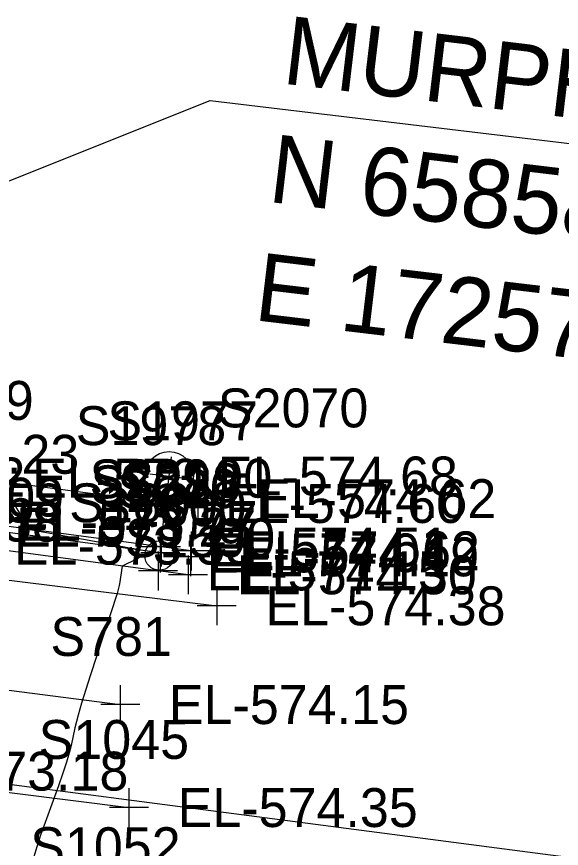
# Model space of a CAD drawing. Extents: x 1724534 to 1727318, y 657156 to 660047.
# Drawn here: x 1725905.5 to 1725961.5, y 658565.7 to 658651.2 of the extents above; entities that cross this region are included whole.
import ezdxf

# ---------------------------------------------------------------- set-up
doc = ezdxf.new("R2010")
doc.units = 0
for name, color, linetype in [('SURVEY - CENTERLINE - Preliminary Text', 7, 'Continuous'), ('SURVEY - CONTOURS - Intermediate with optional Text', 7, 'Continuous'), ('SURVEY - DTM - Breaklines', 7, 'Continuous'), ('SURVEY - DTM - Breaklines - Points - Elevations', 7, 'Continuous'), ('SURVEY - DTM - Breaklines - Points - Locators', 7, 'Continuous'), ('SURVEY - DTM - Breaklines - Points - Numbers', 7, 'Continuous'), ('SURVEY - TRAFFIC CONTROL - Pavement Marking - Points - Elevations', 7, 'Continuous'), ('SURVEY - TRAFFIC CONTROL - Pavement Marking - Points - Locators', 7, 'Continuous'), ('SURVEY - TRAFFIC CONTROL - Pavement Marking - Points - Numbers', 7, 'Continuous'), ('SURVEY - TRAFFIC CONTROL - Pavement Marking with Text', 7, 'Continuous'), ('SURVEY - TRANSPORTATION - Features', 7, 'Continuous'), ('SURVEY - TRANSPORTATION - Features - Points - Elevations', 7, 'Continuous'), ('SURVEY - TRANSPORTATION - Features - Points - Locators', 7, 'Continuous'), ('SURVEY - TRANSPORTATION - Features - Points - Numbers', 7, 'Continuous'), ('SURVEY - TRANSPORTATION - Roads', 7, 'Continuous'), ('SURVEY - TRANSPORTATION - Roads - Points - Elevations', 7, 'Continuous'), ('SURVEY - TRANSPORTATION - Roads - Points - Locators', 7, 'Continuous'), ('SURVEY - TRANSPORTATION - Roads - Points - Numbers', 7, 'Continuous'), ('SURVEY - UTILITIES - Electric (Lighting) - Points - Elevations', 7, 'Continuous'), ('SURVEY - UTILITIES - Electric (Lighting) - Points - Locators', 7, 'Continuous'), ('SURVEY - UTILITIES - Electric (Lighting) - Points - Numbers', 7, 'Continuous'), ('SURVEY - UTILITIES - Electric (Lighting) with Text', 7, 'Continuous'), ('SURVEY - UTILITIES - Water with Text', 7, 'Continuous')]:
    doc.layers.add(name, color=color, linetype=linetype)

msp = doc.modelspace()

# ---------------------------------------------------------------- linework, layer by layer
at = {"layer": 'SURVEY - CENTERLINE - Preliminary Text'}
for p, q in [((1725772.853, 658581.708), (1725925.415, 658642.543)), ((1725925.415, 658642.543), (1726126.989, 658618.518))]:
    msp.add_line(p, q, dxfattribs=at)
at = {"layer": 'SURVEY - CONTOURS - Intermediate with optional Text'}
msp.add_lwpolyline([(1725904.993, 658601.596), (1725905.542, 658600.595), (1725905.788, 658600.157), (1725905.89, 658599.981), (1725906.23, 658599.394), (1725906.31, 658599.252), (1725906.379, 658599.122), (1725906.439, 658599.005), (1725906.695, 658598.491), (1725909.713, 658597.944), (1725911.185, 658597.675), (1725912.581, 658597.422), (1725913.679, 658597.22), (1725914.63, 658597.045), (1725916.941, 658596.621), (1725917.331, 658596.548), (1725919.295, 658596.185), (1725918.267, 658595.646), (1725917.825, 658595.423), (1725916.347, 658594.697), (1725916.185, 658593.547), (1725916.15, 658593.309), (1725916.113, 658593.089), (1725916.076, 658592.886), (1725916.036, 658592.701), (1725915.849, 658591.877), (1725913.078, 658583.42), (1725912.174, 658580.602), (1725911.991, 658580.005), (1725911.818, 658579.385), (1725911.656, 658578.741), (1725911.504, 658578.075), (1725911.111, 658576.269), (1725910.918, 658575.5), (1725910.636, 658574.55), (1725910.262, 658573.419), (1725909.799, 658572.105), (1725908.441, 658568.361), (1725907.972, 658567.03), (1725907.584, 658565.844), (1725907.275, 658564.803)], dxfattribs=at)
at = {"layer": 'SURVEY - DTM - Breaklines'}
msp.add_lwpolyline([(1725923.442, 658596.261), (1725920.349, 658596.664), (1725900.537, 658599.315), (1725880.703, 658601.788), (1725860.867, 658604.256), (1725841.017, 658606.73), (1725821.164, 658609.108), (1725805.637, 658611.084), (1725785.8, 658613.524), (1725762.697, 658616.458), (1725748.853, 658618.143), (1725745.613, 658618.535), (1725725.762, 658620.955), (1725705.909, 658623.419), (1725686.061, 658625.875)], dxfattribs=at)
at = {"layer": 'SURVEY - DTM - Breaklines - Points - Locators'}
for p, q in [((1725920.349, 658598.664), (1725920.349, 658594.664)), ((1725923.442, 658598.261), (1725923.442, 658594.261)), ((1725922.349, 658596.664), (1725918.349, 658596.664)), ((1725925.442, 658596.261), (1725921.442, 658596.261))]:
    msp.add_line(p, q, dxfattribs=at)
at = {"layer": 'SURVEY - TRAFFIC CONTROL - Pavement Marking - Points - Locators'}
for p, q in [((1725916.153, 658582.463), (1725916.153, 658578.463)), ((1725918.153, 658580.463), (1725914.153, 658580.463)), ((1725917.054, 658571.88), (1725917.054, 658567.88)), ((1725919.054, 658569.88), (1725915.054, 658569.88))]:
    msp.add_line(p, q, dxfattribs=at)
at = {"layer": 'SURVEY - TRAFFIC CONTROL - Pavement Marking with Text'}
for points in [[(1725469.93, 658636.195), (1725476.311, 658635.371), (1725478.295, 658635.122), (1725516.011, 658630.481), (1725599.369, 658620.164), (1725678.757, 658610.338), (1725738.298, 658602.97), (1725780.716, 658597.719), (1725790.639, 658596.491), (1725852.127, 658588.674), (1725871.961, 658586.151), (1725916.153, 658580.463)], [(1725691.276, 658598.614), (1725717.028, 658595.036), (1725719.009, 658594.766), (1725742.941, 658591.917), (1725766.76, 658588.985), (1725807.969, 658583.629), (1725837.716, 658579.798), (1725859.541, 658577.092), (1725887.31, 658573.624), (1725917.054, 658569.88)]]:
    msp.add_lwpolyline(points, dxfattribs=at)
at = {"layer": 'SURVEY - TRANSPORTATION - Features'}
for points in [[(1725923.364, 658595.652), (1725920.271, 658596.054), (1725900.459, 658598.705), (1725880.625, 658601.178), (1725860.79, 658603.646), (1725840.941, 658606.12), (1725821.088, 658608.498), (1725805.562, 658610.474), (1725785.723, 658612.914), (1725762.62, 658615.849), (1725748.776, 658617.533), (1725745.535, 658617.925), (1725725.684, 658620.345), (1725705.833, 658622.809), (1725685.985, 658625.265)], [(1725924.124, 658601.632), (1725920.917, 658601.133), (1725901.098, 658603.73), (1725881.263, 658606.193), (1725861.425, 658608.639), (1725841.56, 658611.106), (1725821.706, 658613.473), (1725806.126, 658615.02), (1725786.298, 658617.46), (1725763.169, 658620.191), (1725751.211, 658621.652), (1725751.19, 658622.534), (1725749.441, 658623.208)], [(1725923.129, 658593.802), (1725920.036, 658594.204), (1725900.224, 658596.854), (1725880.377, 658599.224), (1725860.524, 658601.554), (1725840.686, 658604.065), (1725820.833, 658606.443), (1725805.311, 658608.457), (1725785.478, 658610.975), (1725762.374, 658613.908), (1725762.62, 658615.849)]]:
    msp.add_lwpolyline(points, dxfattribs=at)
at = {"layer": 'SURVEY - TRANSPORTATION - Features - Points - Locators'}
for p, q in [((1725924.124, 658603.632), (1725924.124, 658599.632)), ((1725920.917, 658603.133), (1725920.917, 658599.133)), ((1725922.917, 658601.133), (1725918.917, 658601.133)), ((1725926.124, 658601.632), (1725922.124, 658601.632)), ((1725920.271, 658598.054), (1725920.271, 658594.054)), ((1725923.364, 658597.652), (1725923.364, 658593.652)), ((1725922.271, 658596.054), (1725918.271, 658596.054)), ((1725920.036, 658596.204), (1725920.036, 658592.204)), ((1725925.364, 658595.652), (1725921.364, 658595.652)), ((1725923.129, 658595.802), (1725923.129, 658591.802)), ((1725922.036, 658594.204), (1725918.036, 658594.204)), ((1725925.129, 658593.802), (1725921.129, 658593.802))]:
    msp.add_line(p, q, dxfattribs=at)
at = {"layer": 'SURVEY - TRANSPORTATION - Roads'}
msp.add_lwpolyline([(1725603.861, 658630.44), (1725726.921, 658615.268), (1725763.101, 658610.806), (1725790.88, 658607.344), (1725824.612, 658603.138), (1725872.227, 658597.261), (1725926.076, 658590.615)], dxfattribs=at)
at = {"layer": 'SURVEY - TRANSPORTATION - Roads - Points - Locators'}
for p, q in [((1725926.076, 658592.615), (1725926.076, 658588.615)), ((1725928.076, 658590.615), (1725924.076, 658590.615))]:
    msp.add_line(p, q, dxfattribs=at)
at = {"layer": 'SURVEY - UTILITIES - Electric (Lighting) - Points - Locators'}
for p, q in [((1725920.946, 658601.973), (1725921.432, 658605.943)), ((1725919.204, 658604.201), (1725923.174, 658603.715))]:
    msp.add_line(p, q, dxfattribs=at)
at = {"layer": 'SURVEY - UTILITIES - Electric (Lighting) with Text'}
msp.add_line((1725920.358, 658597.269), (1725920.874, 658601.488), dxfattribs=at)
for centre, radius in [((1725921.178, 658603.97), 2.5), ((1725920.176, 658595.781), 1.5)]:
    msp.add_circle(centre, radius, dxfattribs=at)
at = {"layer": 'SURVEY - UTILITIES - Water with Text'}
msp.add_lwpolyline([(1725847.724, 658579.712), (1725982.184, 658562.183), (1725988.335, 658559.963), (1726011.571, 658556.88)], dxfattribs=at)

# ---------------------------------------------------------------- texts
at = {"layer": 'SURVEY - CENTERLINE - Preliminary Text'}
for s, p in [('MURPHY ROAD STA. 106+12.23', (1725932.677, 658644.321)), ('N 658581.7082', (1725931.227, 658632.157)), ('E 1725772.8534', (1725929.777, 658619.993))]:
    msp.add_text(s, height=7, rotation=353.20328, dxfattribs=at).set_placement(p)
at = {"layer": 'SURVEY - DTM - Breaklines - Points - Elevations'}
for s, p in [('EL-573.09', (1725885.703, 658599.788)), ('EL-573.77', (1725905.537, 658597.315)), ('EL-574.51', (1725925.349, 658594.664)), ('EL-574.62', (1725928.442, 658594.261))]:
    msp.add_text(s, height=4, dxfattribs=at).set_placement(p)
at = {"layer": 'SURVEY - DTM - Breaklines - Points - Numbers'}
for s, p in [('S289', (1725912.997, 658601.664)), ('S288', (1725916.059, 658601.261))]:
    msp.add_text(s, height=4, dxfattribs=at).set_placement(p)
at = {"layer": 'SURVEY - TRAFFIC CONTROL - Pavement Marking - Points - Elevations'}
for s, p in [('EL-574.15', (1725921.153, 658578.463)), ('EL-573.18', (1725892.31, 658571.624)), ('EL-574.35', (1725922.054, 658567.88))]:
    msp.add_text(s, height=4, dxfattribs=at).set_placement(p)
at = {"layer": 'SURVEY - TRAFFIC CONTROL - Pavement Marking - Points - Numbers'}
for s, p in [('S781', (1725908.975, 658585.463)), ('S1045', (1725907.766, 658574.88)), ('S1052', (1725906.899, 658563.855))]:
    msp.add_text(s, height=4, dxfattribs=at).set_placement(p)
at = {"layer": 'SURVEY - TRANSPORTATION - Features - Points - Elevations'}
for s, p in [('EL-573.23', (1725887.263, 658604.193)), ('EL-573.90', (1725907.098, 658601.73)), ('EL-574.62', (1725930.124, 658599.632)), ('EL-572.58', (1725885.625, 658599.178)), ('EL-574.60', (1725926.917, 658599.133)), ('EL-572.58', (1725885.377, 658597.224)), ('EL-573.27', (1725905.459, 658596.705)), ('EL-573.33', (1725905.224, 658594.854)), ('EL-574.04', (1725925.271, 658594.054)), ('EL-574.19', (1725928.364, 658593.652)), ('EL-574.15', (1725925.036, 658592.204)), ('EL-574.30', (1725928.129, 658591.802))]:
    msp.add_text(s, height=4, dxfattribs=at).set_placement(p)
at = {"layer": 'SURVEY - TRANSPORTATION - Features - Points - Numbers'}
for s, p in [('S1979', (1725891.795, 658609.73)), ('S1977', (1725914.836, 658607.632)), ('S1978', (1725911.582, 658607.133)), ('S1802', (1725890.936, 658601.854)), ('S521', (1725913.093, 658601.054)), ('S520', (1725915.855, 658600.652)), ('S1801', (1725910.906, 658599.204)), ('S1800', (1725913.668, 658598.802))]:
    msp.add_text(s, height=4, dxfattribs=at).set_placement(p)
at = {"layer": 'SURVEY - TRANSPORTATION - Roads - Points - Elevations'}
msp.add_text('EL-574.38', height=4, dxfattribs=at).set_placement((1725931.076, 658588.615))
at = {"layer": 'SURVEY - TRANSPORTATION - Roads - Points - Numbers'}
msp.add_text('S1590', height=4, dxfattribs=at).set_placement((1725916.615, 658595.615))
at = {"layer": 'SURVEY - UTILITIES - Electric (Lighting) - Points - Elevations'}
msp.add_text('EL-574.68', height=4, dxfattribs=at).set_placement((1725926.189, 658601.958))
at = {"layer": 'SURVEY - UTILITIES - Electric (Lighting) - Points - Numbers'}
msp.add_text('S2070', height=4, dxfattribs=at).set_placement((1725926.189, 658608.958))

doc.saveas('drawing.dxf')
